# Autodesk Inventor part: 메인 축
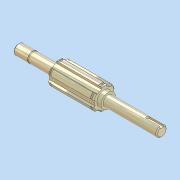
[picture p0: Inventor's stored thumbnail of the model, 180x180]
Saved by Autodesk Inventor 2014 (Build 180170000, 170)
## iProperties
Created: 2012-05
Part Number: 메인 축
Document SubType Name: 모델링
Designer: SeoGD™
Mass: 21.4462 g
Surface Area: 72.5109 cm^2
Volume: 21.4462 cm^3
Density: 1 g/cm^3
Material: 강철, 연강
Appearance: 강철
변환 표준: STEP AP214IS
파일 이름: C:\Users\SeoGD\Desktop\?쒗뿕\硫붿씤 異?.stp
전처리기: Build: 253, Release: 2010 SP1 - Date: Wed 07/29/2009
전송 단위: 밀리미터
불확실성: 0.01
Author: SeoGD™
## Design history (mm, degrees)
sketch "스케치1"
  geometry: L1 (-69.5, 0)-(69.5, 0); L2 (69.5, 0)-(69.5, 5); L3 (69.5, 5)-(55.5, 5); L4 (55.5, 5)-(55.5, 4.8); L5 (55.5, 4.8)-(54.35, 4.8); L6 (54.35, 4.8)-(54.35, 5); L7 (54.35, 5)-(30.5, 5); L8 (30.5, 5)-(30.5, 9); L9 (30.5, 9)-(-13.5, 9); L10 (-13.5, 9)-(-13.5, 7); L11 (-13.5, 7)-(-17.5, 7); L12 (-17.5, 7)-(-17.5, 5); L13 (-17.5, 5)-(-69.5, 5); L14 (-69.5, 5)-(-69.5, 0); 2 further points
  constraints: 28 end point, 9 parallel, 4 collinear, 2 perpendicular, 1 coincident, 1 horizontal, 1 midpoint
  dimensions: "d2" = 1.15 distance between parallel lines of L6 L4; "d3" = 10 diameter of L3 L1; "d4" = 9.6 diameter of L5 L1; "d6" = 44 distance between parallel lines of L10 L8; "d7" = 4 distance between parallel lines of L12 L10; "d8" = 14 diameter of L11 L1; "d9" = 18 diameter of L9 L1; "d33" = 52 distance from line of L12.end L14; "d37" = 39 distance between parallel lines of L8 L2; "d38" = 14 distance between parallel lines of L2 L4
revolve "회전1" sketch "스케치1" stored, may be unused: angle "d10" = 90 deg
sketch "스케치2"
  geometry: L1 (2.5, 10.712)-(2.5, 8.646); L2 (-2.5, 10.712)-(-2.5, 8.646); A1 r 9 centre (0, 0) between (2.5, 8.646) and (-2.5, 8.646) reference; A2 r 11 centre (0, 0) between (2.5, 10.712) and (-2.5, 10.712); 1 further point
  constraints: 4 end point, 4 point on circle, 2 parallel, 1 centre point, 1 coincident, 1 vertical
  dimensions: "d11" = 22 diameter of A2; "d12" = 5 distance between parallel lines of L1 L2
extrude "돌출1" join sketch "스케치2" stored distance "d13" = 10; taper "d14" = 0 deg
chamfer "모따기1" distance "d15" = 1; stored, may be unused: second distance "d16" = 2, angle "d17" = 45 deg
node "작업 평면1"
node "작업 평면2"
sketch "스케치3"
  geometry: L1 (2.5, 10.712)-(2.5, 10.198); L2 (-2.5, 10.712)-(-2.5, 10.198); A1 r 11 centre (0, 0) between (2.5, 10.712) and (-2.5, 10.712) reference; A2 r 10.5 centre (0, 0) between (2.5, 10.198) and (-2.5, 10.198); 1 further point
  constraints: 4 end point, 2 point on circle, 1 centre point, 1 coincident, 1 parallel, 1 vertical
  dimensions: "d19" = 21 diameter of A2
extrude "돌출2" cut sketch "스케치3" distance "d20" = 1.35; taper "d21" = 0 deg
node "작업 평면3"
sketch "스케치4"
  geometry: L1 (-26, -5)-(-26, 5) reference; L2 (-26, 1.5)-(-12.5, 1.5); L3 (-12.5, -1.5)-(-26, -1.5); A1 r 1.5 centre (-12.5, 0) between (-12.5, -1.5) and (-12.5, 1.5); 2 further points
  constraints: 4 end point, 2 perpendicular, 2 point on circle, 2 point on line, 2 tangent, 1 centre point, 1 horizontal alignment, 1 midpoint
  dimensions: "d25" = 3 distance between parallel lines of L3 L2; "d26" = 15 dimension on A1 L1
extrude "돌출3" cut sketch "스케치4" distance "d27" = 1.8; taper "d28" = 0 deg
chamfer "모따기2" distance "d29" = 1; stored, may be unused: second distance "d30" = 2, angle "d31" = 45 deg
node "솔리드1"
node "솔리드 본체"
node "곡면 본체"
mirror "대칭1"
pattern_circular "원형 패턴1" dims "d23" = 360 deg
node "솔리드2"
other parameters: "d18" = -1.65
